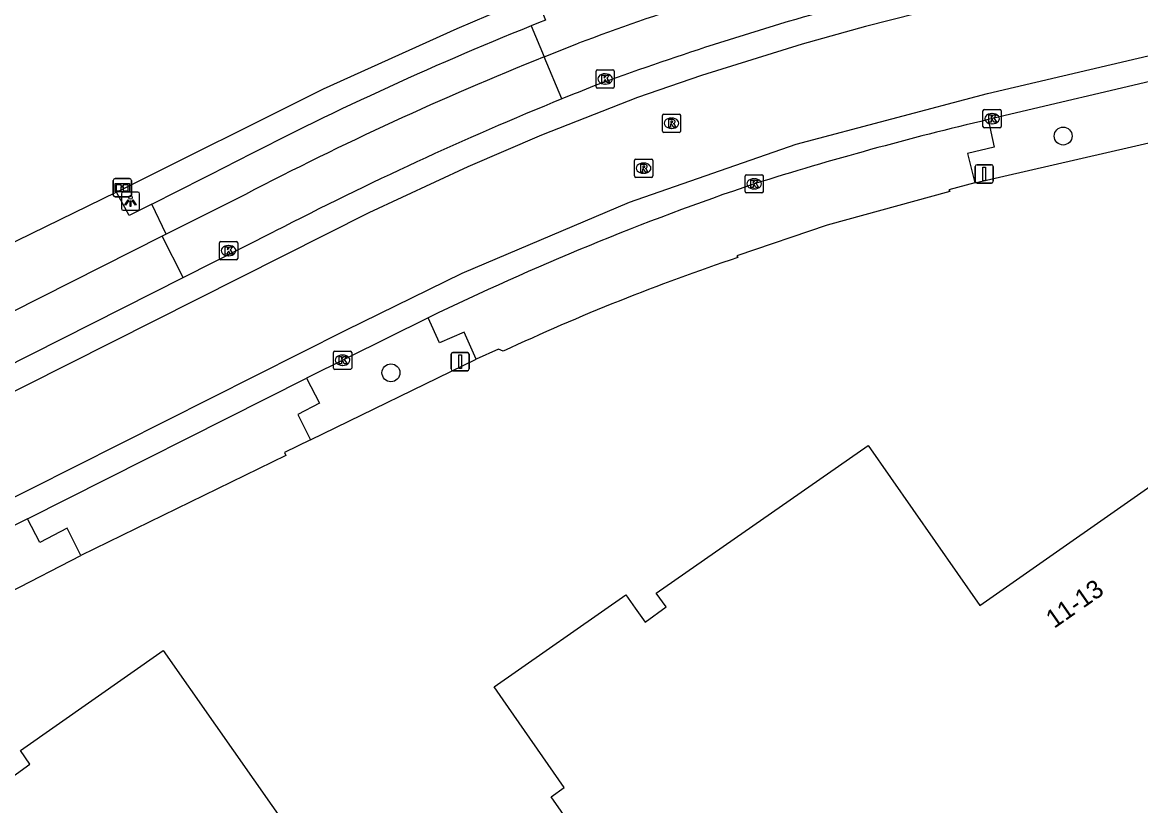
# Model space of a CAD drawing. Extents: x 156651 to 158072, y 387631 to 388990.
# Drawn here: x 157261.4 to 157322.6, y 388342.7 to 388385.5 of the extents above; entities that cross this region are included whole.
import ezdxf

# ---------------------------------------------------------------- set-up
doc = ezdxf.new("R2010")
doc.units = 0
for name, color, linetype in [('IMGEO_Berm_groen', 7, 'Continuous'), ('IMGEO_Boom', 7, 'Continuous'), ('IMGEO_Groenvoorziening', 7, 'Continuous'), ('IMGEO_Informatiebord', 7, 'Continuous'), ('IMGEO_Kolk', 7, 'Continuous'), ('IMGEO_Lichtpunt', 7, 'Continuous'), ('IMGEO_Pand', 7, 'Continuous'), ('IMGEO_Pand_nummerreeks', 7, 'Continuous'), ('IMGEO_Parkeervlak_gesloten', 7, 'Continuous'), ('IMGEO_Rijbaan_lokaal_gesloten', 7, 'Continuous'), ('IMGEO_Rijbaan_lokaal_open', 7, 'Continuous'), ('IMGEO_Rioolput', 7, 'Continuous'), ('IMGEO_Verkeersbordpaal', 7, 'Continuous'), ('IMGEO_Voetpad_open', 7, 'Continuous')]:
    doc.layers.add(name, color=color, linetype=linetype)

msp = doc.modelspace()

# ---------------------------------------------------------------- linework, layer by layer
at = {"layer": 'IMGEO_Berm_groen'}
for points in [[(157313.544, 388376.755), (157330.931, 388380.761), (157335.195, 388381.743)], [(157277.203, 388362.704), (157286.254, 388367.11)], [(157256.833, 388352.351), (157264.626, 388356.371)]]:
    msp.add_lwpolyline(points, dxfattribs=at)
at = {"layer": 'IMGEO_Boom'}
for centre in [(157318.387, 388379.319), (157281.597, 388366.367)]:
    msp.add_circle(centre, 0.489, dxfattribs=at)
at = {"layer": 'IMGEO_Groenvoorziening'}
msp.add_lwpolyline([(157266.572, 388376.245), (157277.916, 388381.91), (157285.218, 388385.202), (157289.505, 388387.041)], dxfattribs=at)
at = {"layer": 'IMGEO_Informatiebord'}
for p, q in [((157266.401, 388376.093), (157266.401, 388376.893)), ((157266.401, 388376.893), (157266.401, 388376.093)), ((157266.501, 388376.993), (157267.291, 388376.993)), ((157267.291, 388376.993), (157266.501, 388376.993)), ((157267.391, 388376.893), (157267.391, 388376.093)), ((157267.391, 388376.093), (157267.391, 388376.893)), ((157267.291, 388375.993), (157266.501, 388375.993)), ((157266.501, 388375.993), (157267.291, 388375.993))]:
    msp.add_line(p, q, dxfattribs=at)
for points in [[(157266.502, 388376.725), (157267.29, 388376.725), (157267.29, 388376.261), (157266.502, 388376.261), (157266.502, 388376.725)], [(157266.567, 388376.66), (157266.567, 388376.326), (157266.842, 388376.326), (157266.843, 388376.539), (157266.947, 388376.54), (157266.948, 388376.326), (157267.225, 388376.326), (157267.225, 388376.66), (157266.949, 388376.66), (157266.949, 388376.58), (157266.843, 388376.58), (157266.843, 388376.66), (157266.567, 388376.66)]]:
    msp.add_lwpolyline(points, dxfattribs=at)
for centre, start, end in [((157266.501, 388376.893), 90, 180), ((157266.501, 388376.893), 90, 180), ((157267.291, 388376.893), 0, 90), ((157267.291, 388376.893), 360, 90), ((157266.501, 388376.093), 180, 270), ((157266.501, 388376.093), 180, 270), ((157267.291, 388376.093), 270, 0), ((157267.291, 388376.093), 270, 0)]:
    msp.add_arc(centre, 0.1, start, end, dxfattribs=at)
at = {"layer": 'IMGEO_Kolk'}
for p, q in [((157292.82, 388382.019), (157292.82, 388382.871)), ((157292.895, 388382.945), (157293.747, 388382.945)), ((157293.821, 388382.871), (157293.821, 388382.019)), ((157293.308, 388382.725), (157293.333, 388382.725)), ((157293.747, 388381.945), (157292.895, 388381.945)), ((157293.331, 388382.165), (157293.306, 388382.165)), ((157313.995, 388379.847), (157313.995, 388380.699)), ((157314.07, 388380.773), (157314.922, 388380.773)), ((157314.483, 388380.553), (157314.508, 388380.553)), ((157314.996, 388380.699), (157314.996, 388379.847)), ((157314.922, 388379.773), (157314.07, 388379.773)), ((157314.506, 388379.993), (157314.481, 388379.993)), ((157300.976, 388376.28), (157300.976, 388377.132)), ((157301.051, 388377.206), (157301.903, 388377.206)), ((157301.464, 388376.986), (157301.489, 388376.986)), ((157301.977, 388377.132), (157301.977, 388376.28)), ((157301.903, 388376.206), (157301.051, 388376.206)), ((157301.487, 388376.426), (157301.462, 388376.426)), ((157272.211, 388372.624), (157272.211, 388373.476)), ((157272.286, 388373.55), (157273.138, 388373.55)), ((157272.699, 388373.33), (157272.724, 388373.33)), ((157273.212, 388373.476), (157273.212, 388372.624)), ((157273.138, 388372.55), (157272.286, 388372.55)), ((157272.722, 388372.77), (157272.697, 388372.77)), ((157278.45, 388366.627), (157278.45, 388367.479)), ((157278.525, 388367.553), (157279.377, 388367.553)), ((157279.451, 388367.479), (157279.451, 388366.627)), ((157278.938, 388367.333), (157278.963, 388367.333)), ((157279.377, 388366.553), (157278.525, 388366.553)), ((157278.961, 388366.773), (157278.936, 388366.773))]:
    msp.add_line(p, q, dxfattribs=at)
for points in [[(157292.82, 388382.019), (157292.82, 388382.871)], [(157292.895, 388382.945), (157293.747, 388382.945)], [(157293.821, 388382.871), (157293.821, 388382.019)], [(157293.141, 388382.645), (157293.264, 388382.645), (157293.264, 388382.494), (157293.394, 388382.645), (157293.558, 388382.645), (157293.412, 388382.494), (157293.565, 388382.245), (157293.413, 388382.245), (157293.328, 388382.409), (157293.264, 388382.342), (157293.264, 388382.245), (157293.141, 388382.245), (157293.141, 388382.645)], [(157293.747, 388381.945), (157292.895, 388381.945)], [(157313.995, 388379.847), (157313.995, 388380.699)], [(157314.07, 388380.773), (157314.922, 388380.773)], [(157314.316, 388380.473), (157314.439, 388380.473), (157314.439, 388380.322), (157314.569, 388380.473), (157314.733, 388380.473), (157314.587, 388380.322), (157314.74, 388380.073), (157314.588, 388380.073), (157314.503, 388380.237), (157314.439, 388380.17), (157314.439, 388380.073), (157314.316, 388380.073), (157314.316, 388380.473)], [(157314.996, 388380.699), (157314.996, 388379.847)], [(157314.922, 388379.773), (157314.07, 388379.773)], [(157300.976, 388376.28), (157300.976, 388377.132)], [(157301.051, 388377.206), (157301.903, 388377.206)], [(157301.297, 388376.906), (157301.42, 388376.906), (157301.42, 388376.755), (157301.55, 388376.906), (157301.714, 388376.906), (157301.568, 388376.755), (157301.721, 388376.506), (157301.569, 388376.506), (157301.484, 388376.67), (157301.42, 388376.603), (157301.42, 388376.506), (157301.297, 388376.506), (157301.297, 388376.906)], [(157301.977, 388377.132), (157301.977, 388376.28)], [(157301.903, 388376.206), (157301.051, 388376.206)], [(157272.211, 388372.624), (157272.211, 388373.476)], [(157272.286, 388373.55), (157273.138, 388373.55)], [(157272.532, 388373.25), (157272.655, 388373.25), (157272.655, 388373.099), (157272.785, 388373.25), (157272.949, 388373.25), (157272.803, 388373.099), (157272.956, 388372.85), (157272.804, 388372.85), (157272.719, 388373.014), (157272.655, 388372.947), (157272.655, 388372.85), (157272.532, 388372.85), (157272.532, 388373.25)], [(157273.212, 388373.476), (157273.212, 388372.624)], [(157273.138, 388372.55), (157272.286, 388372.55)], [(157278.45, 388366.627), (157278.45, 388367.479)], [(157278.525, 388367.553), (157279.377, 388367.553)], [(157279.451, 388367.479), (157279.451, 388366.627)], [(157278.771, 388367.253), (157278.894, 388367.253), (157278.894, 388367.102), (157279.024, 388367.253), (157279.188, 388367.253), (157279.042, 388367.102), (157279.195, 388366.853), (157279.043, 388366.853), (157278.958, 388367.017), (157278.894, 388366.95), (157278.894, 388366.853), (157278.771, 388366.853), (157278.771, 388367.253)], [(157279.377, 388366.553), (157278.525, 388366.553)]]:
    msp.add_lwpolyline(points, dxfattribs=at)
for centre, start, end in [((157292.897, 388382.869), 91.55205, 178.44795), ((157292.897, 388382.869), 91.55205, 178.44795), ((157293.745, 388382.869), 1.55205, 88.44795), ((157293.745, 388382.869), 1.55205, 88.44795), ((157292.897, 388382.021), 181.55205, 268.44795), ((157292.897, 388382.021), 181.55205, 268.44795), ((157293.745, 388382.021), 271.55205, 358.44795), ((157293.745, 388382.021), 271.55205, 358.44795), ((157314.072, 388380.697), 91.55205, 178.44795), ((157314.072, 388380.697), 91.55205, 178.44795), ((157314.92, 388380.697), 1.55205, 88.44795), ((157314.92, 388380.697), 1.55205, 88.44795), ((157314.072, 388379.849), 181.55205, 268.44795), ((157314.072, 388379.849), 181.55205, 268.44795), ((157314.92, 388379.849), 271.55205, 358.44795), ((157314.92, 388379.849), 271.55205, 358.44795), ((157301.053, 388377.13), 91.55205, 178.44795), ((157301.053, 388377.13), 91.55205, 178.44795), ((157301.901, 388377.13), 1.55205, 88.44795), ((157301.901, 388377.13), 1.55205, 88.44795), ((157301.053, 388376.282), 181.55205, 268.44795), ((157301.053, 388376.282), 181.55205, 268.44795), ((157301.901, 388376.282), 271.55205, 358.44795), ((157301.901, 388376.282), 271.55205, 358.44795), ((157272.288, 388373.474), 91.55205, 178.44795), ((157272.288, 388373.474), 91.55205, 178.44795), ((157273.136, 388373.474), 1.55205, 88.44795), ((157273.136, 388373.474), 1.55205, 88.44795), ((157272.288, 388372.626), 181.55205, 268.44795), ((157272.288, 388372.626), 181.55205, 268.44795), ((157273.136, 388372.626), 271.55205, 358.44795), ((157273.136, 388372.626), 271.55205, 358.44795), ((157278.527, 388367.477), 91.55205, 178.44795), ((157278.527, 388367.477), 91.55205, 178.44795), ((157279.375, 388367.477), 1.55205, 88.44795), ((157279.375, 388367.477), 1.55205, 88.44795), ((157278.527, 388366.629), 181.55205, 268.44795), ((157278.527, 388366.629), 181.55205, 268.44795), ((157279.375, 388366.629), 271.55205, 358.44795), ((157279.375, 388366.629), 271.55205, 358.44795)]:
    msp.add_arc(centre, 0.0765, start, end, dxfattribs=at)
for centre, major_axis, ratio, start_param, end_param in [((157293.307, 388382.445), (-0.387, 0.002), 0.722429, 4.712389, 7.853982), ((157293.332, 388382.445), (-0.39, 0.002), 0.717154, 1.570796, 4.712389), ((157314.482, 388380.273), (-0.387, 0.002), 0.722429, 4.712389, 7.853982), ((157314.507, 388380.273), (-0.39, 0.002), 0.717154, 1.570796, 4.712389), ((157301.463, 388376.706), (-0.387, 0.002), 0.722429, 4.712389, 7.853982), ((157301.488, 388376.706), (-0.39, 0.002), 0.717154, 1.570796, 4.712389), ((157272.698, 388373.05), (-0.387, 0.002), 0.722429, 4.712389, 7.853982), ((157272.723, 388373.05), (-0.39, 0.002), 0.717154, 1.570796, 4.712389), ((157278.937, 388367.053), (-0.387, 0.002), 0.722429, 4.712389, 7.853982), ((157278.962, 388367.053), (-0.39, 0.002), 0.717154, 1.570796, 4.712389)]:
    msp.add_ellipse(centre, major_axis=major_axis, ratio=ratio, start_param=start_param, end_param=end_param, dxfattribs=at)
at = {"layer": 'IMGEO_Lichtpunt'}
for p, q in [((157266.845, 388376.163), (157266.845, 388375.356)), ((157266.845, 388376.163), (157266.845, 388375.356)), ((157267.747, 388376.258), (157266.939, 388376.258)), ((157267.747, 388376.258), (157266.939, 388376.258)), ((157267.841, 388375.356), (157267.841, 388376.163)), ((157267.841, 388375.356), (157267.841, 388376.163)), ((157266.939, 388375.262), (157267.747, 388375.262)), ((157266.939, 388375.262), (157267.747, 388375.262))]:
    msp.add_line(p, q, dxfattribs=at)
for points in [[(157267.219, 388375.827), (157267.258, 388375.799), (157267.07, 388375.537), (157267.032, 388375.564), (157267.219, 388375.827)], [(157267.321, 388375.779), (157267.368, 388375.779), (157267.368, 388375.457), (157267.321, 388375.457), (157267.321, 388375.779)], [(157267.431, 388375.799), (157267.469, 388375.826), (157267.656, 388375.564), (157267.617, 388375.536), (157267.431, 388375.799)]]:
    msp.add_lwpolyline(points, dxfattribs=at)
msp.add_circle((157267.344, 388375.961), 0.0994, dxfattribs=at)
for centre, start, end in [((157266.939, 388376.163), 90, 180), ((157266.939, 388376.163), 90, 180), ((157267.747, 388376.163), 0, 90), ((157267.747, 388376.163), 0, 90), ((157266.939, 388375.356), 180, 270), ((157266.939, 388375.356), 180, 270), ((157267.747, 388375.356), 270, 0), ((157267.747, 388375.356), 270, 360)]:
    msp.add_arc(centre, 0.0946, start, end, dxfattribs=at)
at = {"layer": 'IMGEO_Pand'}
for points in [[(157317.872, 388303.816), (157293.226, 388339.068), (157290.36, 388343.165), (157291.085, 388343.679), (157287.747, 388348.47), (157287.246, 388349.18), (157294.453, 388354.218), (157294.958, 388353.483), (157295.503, 388352.727), (157296.655, 388353.559), (157296.115, 388354.309), (157307.711, 388362.394), (157313.827, 388353.633), (157325.013, 388361.46)], [(157272.979, 388293.284), (157246.983, 388330.471), (157244.119, 388334.568), (157249.628, 388338.397), (157259.448, 388345.224), (157260.377, 388343.895), (157261.844, 388344.947), (157261.316, 388345.705), (157269.124, 388351.173), (157271.995, 388347.08), (157297.64, 388310.51), (157272.979, 388293.284)]]:
    msp.add_lwpolyline(points, dxfattribs=at)
at = {"layer": 'IMGEO_Parkeervlak_gesloten'}
for points in [[(157334.453, 388384.963), (157314.28, 388380.221)], [(157283.638, 388369.376), (157276.977, 388366.075)], [(157261.706, 388358.373), (157255.025, 388355.011)]]:
    msp.add_lwpolyline(points, dxfattribs=at)
at = {"layer": 'IMGEO_Rijbaan_lokaal_gesloten'}
for points in [[(157427.649, 388413.564), (157313.182, 388386.746), (157307.564, 388385.322), (157304.11, 388384.347), (157298.594, 388382.628), (157295.094, 388381.431), (157289.829, 388379.374), (157285.802, 388377.632), (157280.387, 388375.114), (157169.957, 388319.498), (157169.378, 388320.773)], [(157171.244, 388314.319), (157180.605, 388319.095), (157279.127, 388368.703), (157285.498, 388371.81), (157294.645, 388375.709), (157303.766, 388378.867), (157314.242, 388381.65), (157428.83, 388408.527)], [(157270.223, 388371.575), (157275.25, 388374.107)], [(157258.616, 388365.727), (157270.223, 388371.575)]]:
    msp.add_lwpolyline(points, dxfattribs=at)
for centre, radius, start, end in [((157352.682, 388218.748), 173.976, 105.62649, 110.16157), ((157374.09, 388177.124), 220.502, 111.65572, 112.1489), ((157363.738, 388202.989), 192.644, 112.19765, 117.34431)]:
    msp.add_arc(centre, radius, start, end, dxfattribs=at)
at = {"layer": 'IMGEO_Rijbaan_lokaal_open'}
for points in [[(157314.28, 388380.221), (157314.618, 388378.716), (157313.15, 388378.361), (157313.544, 388376.755)], [(157313.544, 388376.755), (157312.136, 388376.386), (157312.19, 388376.29), (157305.462, 388374.438), (157300.531, 388372.775), (157300.578, 388372.669)], [(157286.254, 388367.11), (157285.601, 388368.584), (157284.262, 388368.01), (157283.638, 388369.376)], [(157287.748, 388367.548), (157287.476, 388367.66), (157286.254, 388367.11)], [(157261.706, 388358.373), (157276.977, 388366.075)], [(157276.977, 388366.075), (157277.686, 388364.713), (157276.504, 388364.091), (157277.203, 388362.704)], [(157277.203, 388362.704), (157275.769, 388361.999), (157275.844, 388361.85), (157264.626, 388356.371)], [(157264.626, 388356.371), (157263.87, 388357.861), (157262.374, 388357.083), (157261.706, 388358.373)]]:
    msp.add_lwpolyline(points, dxfattribs=at)
for centre, radius, start, end in [((157357.91, 388196.23), 189.093, 103.34015, 107.36387), ((157351.095, 388230.579), 154.321, 108.75504, 115.92023), ((157338.403, 388259.27), 119.541, 108.44663, 115.07147)]:
    msp.add_arc(centre, radius, start, end, dxfattribs=at)
at = {"layer": 'IMGEO_Rioolput'}
for p, q in [((157296.452, 388379.595), (157296.452, 388380.447)), ((157296.527, 388380.521), (157297.379, 388380.521)), ((157297.453, 388380.447), (157297.453, 388379.595)), ((157296.963, 388379.741), (157296.938, 388379.741)), ((157296.94, 388380.301), (157296.965, 388380.301)), ((157297.379, 388379.521), (157296.527, 388379.521)), ((157294.924, 388377.135), (157294.924, 388377.987)), ((157294.999, 388378.061), (157295.851, 388378.061)), ((157295.925, 388377.987), (157295.925, 388377.135)), ((157295.435, 388377.281), (157295.41, 388377.281)), ((157295.412, 388377.841), (157295.437, 388377.841)), ((157295.851, 388377.061), (157294.999, 388377.061))]:
    msp.add_line(p, q, dxfattribs=at)
for points in [[(157296.452, 388379.595), (157296.452, 388380.447)], [(157296.527, 388380.521), (157297.379, 388380.521)], [(157297.453, 388380.447), (157297.453, 388379.595)], [(157297.041, 388380.219), (157296.789, 388380.221), (157296.789, 388379.821)], [(157296.789, 388379.821), (157296.913, 388379.821), (157296.913, 388379.983), (157296.924, 388379.983)], [(157296.967, 388380.14), (157296.913, 388380.14), (157296.913, 388380.059)], [(157296.913, 388380.059), (157296.965, 388380.059)], [(157296.971, 388379.954), (157297.042, 388379.821), (157297.182, 388379.821), (157297.117, 388379.947)], [(157297.379, 388379.521), (157296.527, 388379.521)], [(157294.924, 388377.135), (157294.924, 388377.987)], [(157294.999, 388378.061), (157295.851, 388378.061)], [(157295.925, 388377.987), (157295.925, 388377.135)], [(157295.513, 388377.759), (157295.261, 388377.761), (157295.261, 388377.361)], [(157295.261, 388377.361), (157295.385, 388377.361), (157295.385, 388377.523), (157295.396, 388377.523)], [(157295.439, 388377.68), (157295.385, 388377.68), (157295.385, 388377.599)], [(157295.385, 388377.599), (157295.437, 388377.599)], [(157295.443, 388377.494), (157295.514, 388377.361), (157295.654, 388377.361), (157295.589, 388377.487)], [(157295.851, 388377.061), (157294.999, 388377.061)]]:
    msp.add_lwpolyline(points, dxfattribs=at)
for centre, radius, start, end in [((157296.529, 388380.445), 0.0765, 91.55205, 178.44795), ((157296.529, 388380.445), 0.0765, 91.55205, 178.44795), ((157297.377, 388380.445), 0.0765, 1.55205, 88.44795), ((157297.377, 388380.445), 0.0765, 1.55205, 88.44795), ((157296.923, 388379.93), 0.0533, 26.02933, 88.69889), ((157296.949, 388380.248), 0.19, 274.7715, 282.96867), ((157296.973, 388380.044), 0.0964, 77.00612, 93.18647), ((157296.987, 388380.101), 0.0378, 276.66336, 79.67722), ((157297.04, 388380.109), 0.109, 350.36119, 89.41601), ((157297.038, 388380.109), 0.112, 277.58423, 350.98172), ((157297.022, 388379.894), 0.108, 29.51342, 73.79051), ((157296.529, 388379.597), 0.0765, 181.55205, 268.44795), ((157296.529, 388379.597), 0.0765, 181.55205, 268.44795), ((157297.377, 388379.597), 0.0765, 271.55205, 358.44795), ((157297.377, 388379.597), 0.0765, 271.55205, 358.44795), ((157295.001, 388377.985), 0.0765, 91.55205, 178.44795), ((157295.001, 388377.985), 0.0765, 91.55205, 178.44795), ((157295.849, 388377.985), 0.0765, 1.55205, 88.44795), ((157295.849, 388377.985), 0.0765, 1.55205, 88.44795), ((157295.395, 388377.47), 0.0533, 26.02933, 88.69889), ((157295.421, 388377.788), 0.19, 274.7715, 282.96867), ((157295.445, 388377.584), 0.0964, 77.00612, 93.18647), ((157295.459, 388377.641), 0.0378, 276.66336, 79.67722), ((157295.512, 388377.649), 0.109, 350.36119, 89.41601), ((157295.51, 388377.649), 0.112, 277.58423, 350.98172), ((157295.494, 388377.434), 0.108, 29.51342, 73.79051), ((157295.001, 388377.137), 0.0765, 181.55205, 268.44795), ((157295.001, 388377.137), 0.0765, 181.55205, 268.44795), ((157295.849, 388377.137), 0.0765, 271.55205, 358.44795), ((157295.849, 388377.137), 0.0765, 271.55205, 358.44795)]:
    msp.add_arc(centre, radius, start, end, dxfattribs=at)
for centre, major_axis, ratio, start_param, end_param in [((157296.939, 388380.021), (-0.387, 0.002), 0.722429, 4.712389, 7.853982), ((157296.964, 388380.021), (-0.39, 0.002), 0.717154, 1.570796, 4.712389), ((157295.411, 388377.561), (-0.387, 0.002), 0.722429, 4.712389, 7.853982), ((157295.436, 388377.561), (-0.39, 0.002), 0.717154, 1.570796, 4.712389)]:
    msp.add_ellipse(centre, major_axis=major_axis, ratio=ratio, start_param=start_param, end_param=end_param, dxfattribs=at)
at = {"layer": 'IMGEO_Verkeersbordpaal'}
for p, q in [((157313.573, 388376.85), (157313.573, 388377.65)), ((157313.573, 388377.65), (157313.573, 388376.85)), ((157313.673, 388377.75), (157314.463, 388377.75)), ((157314.463, 388377.75), (157313.673, 388377.75)), ((157314.563, 388377.65), (157314.563, 388376.85)), ((157314.563, 388376.85), (157314.563, 388377.65)), ((157314.463, 388376.75), (157313.673, 388376.75)), ((157313.673, 388376.75), (157314.463, 388376.75)), ((157284.889, 388366.577), (157284.889, 388367.377)), ((157284.889, 388367.377), (157284.889, 388366.577)), ((157284.989, 388367.477), (157285.779, 388367.477)), ((157285.779, 388367.477), (157284.989, 388367.477)), ((157285.879, 388367.377), (157285.879, 388366.577)), ((157285.879, 388366.577), (157285.879, 388367.377)), ((157285.779, 388366.477), (157284.989, 388366.477)), ((157284.989, 388366.477), (157285.779, 388366.477))]:
    msp.add_line(p, q, dxfattribs=at)
for points in [[(157313.993, 388377.625), (157314.143, 388377.625), (157314.143, 388376.875), (157313.993, 388376.875), (157313.993, 388377.625)], [(157285.309, 388367.352), (157285.459, 388367.352), (157285.459, 388366.602), (157285.309, 388366.602), (157285.309, 388367.352)]]:
    msp.add_lwpolyline(points, dxfattribs=at)
for centre, start, end in [((157313.673, 388377.65), 90, 180), ((157313.673, 388377.65), 90, 180), ((157314.463, 388377.65), 0, 90), ((157314.463, 388377.65), 360, 90), ((157313.673, 388376.85), 180, 270), ((157313.673, 388376.85), 180, 270), ((157314.463, 388376.85), 270, 0), ((157314.463, 388376.85), 270, 0), ((157284.989, 388367.377), 90, 180), ((157284.989, 388367.377), 90, 180), ((157285.779, 388367.377), 0, 90), ((157285.779, 388367.377), 360, 90), ((157284.989, 388366.577), 180, 270), ((157284.989, 388366.577), 180, 270), ((157285.779, 388366.577), 270, 0), ((157285.779, 388366.577), 270, 0)]:
    msp.add_arc(centre, 0.1, start, end, dxfattribs=at)
at = {"layer": 'IMGEO_Voetpad_open'}
for points in [[(157289.505, 388387.041), (157290.056, 388385.662), (157289.667, 388385.507), (157289.279, 388385.351)], [(157289.279, 388385.351), (157289.978, 388383.652)], [(157289.978, 388383.652), (157291.863, 388384.397)], [(157290.957, 388381.355), (157289.978, 388383.652)], [(157268.519, 388375.599), (157272.839, 388377.776)], [(157266.572, 388376.245), (157257.229, 388371.691)], [(157268.519, 388375.599), (157267.264, 388374.967), (157266.572, 388376.245)], [(157273.637, 388376.128), (157269.305, 388373.947)], [(157269.305, 388373.947), (157268.519, 388375.599)], [(157269.085, 388373.836), (157257.475, 388367.992)], [(157269.305, 388373.947), (157269.085, 388373.836)], [(157270.223, 388371.575), (157269.085, 388373.836)]]:
    msp.add_lwpolyline(points, dxfattribs=at)
for centre, radius, start, end in [((157350.903, 388226.449), 168.622, 105.7584, 110.49527), ((157358.708, 388213.041), 185.772, 111.94616, 117.53116), ((157357.773, 388214.903), 181.858, 111.88799, 117.55819)]:
    msp.add_arc(centre, radius, start, end, dxfattribs=at)

# ---------------------------------------------------------------- texts
at = {"layer": 'IMGEO_Pand_nummerreeks'}
msp.add_text('11-13', height=1, rotation=34.98102, dxfattribs=at).set_placement((157317.893, 388352.349))

doc.saveas('drawing.dxf')
